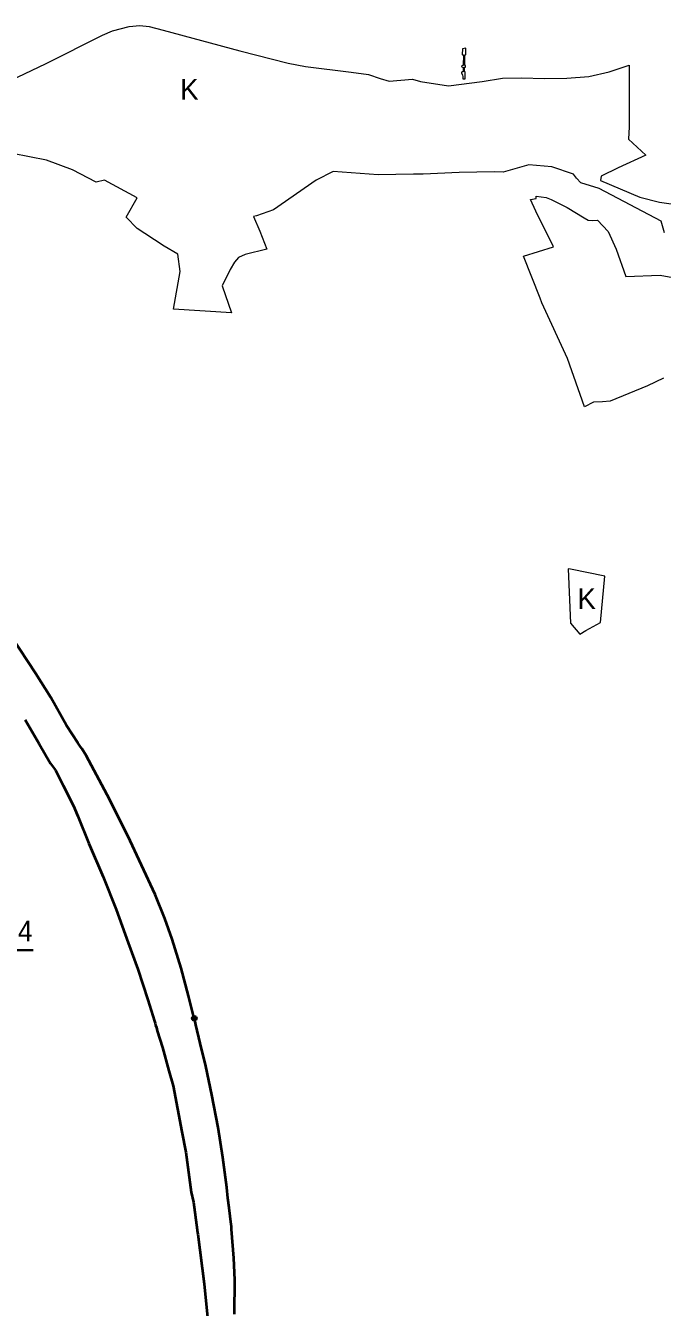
# Model space of a CAD drawing. Extents: x -650276 to -642489, y -1074425 to -1066658.
# Drawn here: x -645214 to -644472, y -1070307 to -1068813 of the extents above; entities that cross this region are included whole.
import ezdxf

# ---------------------------------------------------------------- set-up
doc = ezdxf.new("R2010")
doc.units = 0
doc.header["$LTSCALE"] = 9.6
doc.header["$PDMODE"] = 32
doc.header["$PDSIZE"] = 4.8
for name, color, linetype, lineweight in [('1', 7, 'Continuous', 13), ('43', 7, 'Continuous', 13), ('44', 7, 'Continuous', 40), ('47', 7, 'Continuous', 13), ('62', 7, 'Continuous', 35)]:
    doc.layers.add(name, color=color, linetype=linetype, lineweight=lineweight)

msp = doc.modelspace()

# ---------------------------------------------------------------- linework, layer by layer
at = {"layer": '1'}
for points in [[(-644701.42, -1068861.72), (-644701.38, -1068859.71), (-644702.34, -1068859.68), (-644702.08, -1068847.23), (-644701.42, -1068847.26), (-644701.09, -1068846.91), (-644700.9, -1068839.57), (-644704.8, -1068840.1), (-644705.08, -1068846.84), (-644704.81, -1068847.09), (-644703.68, -1068847.15), (-644704, -1068859.63)], [(-644706.19, -1068867.95), (-644706.2, -1068868.36), (-644704.91, -1068870.88)], [(-644703.94, -1068861.63), (-644704.08, -1068867.01), (-644705.38, -1068867.01), (-644705.95, -1068867.45), (-644706.19, -1068867.95)], [(-644705.53, -1068860.05), (-644706.03, -1068860.61), (-644705.56, -1068861.19), (-644704.79, -1068861.59), (-644703.94, -1068861.63)], [(-644704, -1068859.63), (-644704.74, -1068859.69), (-644705.53, -1068860.05)], [(-644704.91, -1068870.88), (-644704.56, -1068872.46), (-644704.63, -1068875.27)], [(-644704.63, -1068875.27), (-644703.98, -1068875.29), (-644701.79, -1068875.14), (-644701.59, -1068867.03), (-644702.51, -1068867.03)], [(-644702.51, -1068867.03), (-644702.41, -1068861.69), (-644701.42, -1068861.72)]]:
    msp.add_lwpolyline(points, dxfattribs=at)
at = {"layer": '44'}
for points in [[(-645017.46, -1069970.61), (-645018.28, -1069967.49), (-645024.45, -1069944.43), (-645032.85, -1069912.07), (-645043.5, -1069878.37), (-645051.78, -1069854.2), (-645063.26, -1069825.99), (-645095.1, -1069757.62), (-645118.98, -1069710.08), (-645143.56, -1069664.05), (-645148.8, -1069656.1), (-645150.3, -1069653.84), (-645153.33, -1069649.24), (-645166.67, -1069629), (-645184.88, -1069596.58), (-645202.56, -1069568.23), (-645230.1, -1069525.98)], [(-645214.76, -1069622.37), (-645198.41, -1069650.49), (-645185.17, -1069673.38), (-645179.12, -1069681.3), (-645170.3, -1069698.91), (-645158.43, -1069722.61), (-645153.44, -1069734.71), (-645140.27, -1069766.68), (-645123.84, -1069805.38), (-645108.74, -1069843.58), (-645094.42, -1069882.65), (-645083.31, -1069913.37), (-645071.53, -1069948.89), (-645063.96, -1069973.73), (-645063.23, -1069976.2), (-645062.57, -1069978.46), (-645061.76, -1069981.21), (-645060.612, -1069985.022), (-645054.73, -1070004.56), (-645047.28, -1070031.83), (-645042.27, -1070049.23), (-645032.21, -1070102.73), (-645027.49, -1070126.56), (-645021.14, -1070173.07), (-645018.56, -1070184.92), (-645016.92, -1070196.32), (-645013.77, -1070220.04), (-645013.51, -1070222.04), (-645005.98, -1070280.14), (-645002.308, -1070319.268)], [(-645010.54, -1069999.3), (-645015.548, -1069978.177), (-645016.01, -1069976.23), (-645016.89, -1069972.82), (-645017.46, -1069970.61)], [(-644970.524, -1070315.358), (-644970.36, -1070275.49), (-644971.47, -1070250.14), (-644974, -1070216.2), (-644974.29, -1070213.17), (-644974.49, -1070210.98), (-644976.94, -1070191.41), (-644978.49, -1070180.05), (-644979.57, -1070167.9), (-644984.21, -1070132.81), (-644989.62, -1070097.79), (-644996.88, -1070059.73), (-645004.02, -1070026.44), (-645010.54, -1069999.3)]]:
    msp.add_lwpolyline(points, dxfattribs=at)
msp.add_point((-645017.46, -1069970.61), dxfattribs=at)
at = {"layer": '47'}
for points in [[(-645239.85, -1068880.94), (-645190.22, -1068857.23), (-645124.36, -1068824.11), (-645112.77, -1068819.13), (-645093.56, -1068814.27), (-645081.12, -1068813.15), (-645070.05, -1068814), (-645053.97, -1068818.31), (-644964.45, -1068842.38), (-644908.26, -1068856.91), (-644887.91, -1068860.82), (-644834.84, -1068867.4), (-644814.47, -1068870.12), (-644800.87, -1068874.97), (-644790.41, -1068877.73), (-644763.04, -1068875.63), (-644753.71, -1068878.41), (-644721.29, -1068883.2), (-644681.99, -1068878.15), (-644658.39, -1068874.59), (-644636.55, -1068874.02), (-644608.71, -1068874.78), (-644583.26, -1068874.26), (-644557.75, -1068872.33), (-644533.84, -1068867.2), (-644510.62, -1068859.35), (-644510.567, -1068897.909), (-644510.75, -1068931.16), (-644511.47, -1068945.37), (-644491.31, -1068964.35), (-644523.4, -1068978.98), (-644543.05, -1068988.64), (-644544.02, -1068993.75), (-644498.28, -1069013.19), (-644475.09, -1069018.99), (-644461.74, -1069020.83)], [(-645131.73, -1068995.69), (-645159.37, -1068981.11), (-645189.84, -1068969.91), (-645229.27, -1068962.28), (-645232.4, -1068961.67), (-645255.21, -1068962.49), (-645275.45, -1068964.38), (-645292.77, -1068966.91), (-645311.99, -1068972.74), (-645328.55, -1068980.37), (-645350.17, -1068993.33), (-645371.35, -1069010.64), (-645396.53, -1069030.88)], [(-644473.222, -1069040.994), (-644545.54, -1069003.12), (-644567.09, -1068996.26), (-644572.05, -1068991.08), (-644575.29, -1068986.48), (-644600.67, -1068977.77), (-644627.41, -1068975.6), (-644657.61, -1068983.91), (-644667.57, -1068983.47), (-644708.6, -1068984.54), (-644750.67, -1068986.34), (-644761.88, -1068986.27), (-644803.31, -1068986.97), (-644855.56, -1068983.38), (-644875.57, -1068993.47), (-644925.35, -1069027.75), (-644944.9, -1069035.04), (-644948.575, -1069035.675)], [(-644948.575, -1069035.675), (-644941.27, -1069052.9), (-644932.95, -1069073.65), (-644958.25, -1069079.99), (-644965.95, -1069083.67), (-644970.84, -1069088.8), (-644975.56, -1069097.564), (-644985.15, -1069116.67), (-644974.34, -1069147.85), (-645041.751, -1069143.816), (-645034.13, -1069099.79), (-645036.87, -1069079.78), (-645052.83, -1069070.4), (-645075.206, -1069055.523), (-645084.19, -1069049.55), (-645096.97, -1069036.63), (-645084.17, -1069013.922), (-645122.25, -1068993.21), (-645131.73, -1068995.69)], [(-644470.64, -1069224), (-644489.27, -1069233.04), (-644532.71, -1069251.12), (-644541.83, -1069251.66), (-644552.01, -1069252.24), (-644562.47, -1069257.56), (-644582.29, -1069201.27), (-644612.3, -1069136.45), (-644614.41, -1069131.08), (-644633.66, -1069082), (-644598.81, -1069071.02), (-644619.54, -1069029.55), (-644625.69, -1069015.84), (-644618.8, -1069014.7), (-644619.1, -1069011.81), (-644607.16, -1069013.56), (-644601.43, -1069015.74), (-644583.05, -1069025.29), (-644563.19, -1069037.21), (-644558.56, -1069039.86), (-644553.62, -1069040.53), (-644547.31, -1069040.11), (-644535.13, -1069053.18), (-644525.83, -1069073.84), (-644514.47, -1069105.62), (-644474.33, -1069104.22), (-644459.82, -1069106.73)], [(-644469.28, -1069054.8), (-644473.222, -1069040.994)]]:
    msp.add_lwpolyline(points, dxfattribs=at)
msp.add_lwpolyline([(-644578.92, -1069446.8), (-644581.87, -1069446.28), (-644579.047, -1069509.608), (-644567.976, -1069522.752), (-644561.24, -1069518.27), (-644543.99, -1069508.88), (-644539, -1069454.88)], close=True, dxfattribs=at)
at = {"layer": '62'}
msp.add_line((-645253.165, -1069890.903), (-645205.454, -1069890.903), dxfattribs=at)
msp.add_lwpolyline([(-645205.454, -1069890.903), (-645253.165, -1069890.903), (-645480.406, -1069576.285), (-645253.165, -1069890.903), (-645466.774, -1069697.69), (-645253.165, -1069890.903), (-645479.043, -1069805.455), (-645253.165, -1069890.903), (-645420.426, -1069951.415), (-645253.165, -1069890.903), (-645348.178, -1070139.662)], dxfattribs=at)

# ---------------------------------------------------------------- texts
at = {"layer": '43'}
for p in [(-645034.002, -1068899.33), (-644570.824, -1069493.226), (-644570.824, -1069493.226)]:
    msp.add_text('K', height=24, dxfattribs=at).set_placement(p)
at = {"layer": '62', "width": 0.95}
msp.add_text('R4', height=24, dxfattribs=at).set_placement((-645245.139, -1069880.683))

doc.saveas('drawing.dxf')
